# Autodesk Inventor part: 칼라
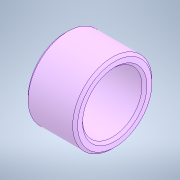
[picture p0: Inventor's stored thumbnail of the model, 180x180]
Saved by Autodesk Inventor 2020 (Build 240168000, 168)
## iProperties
Created: 2024-05
Part Number: 칼라
Material: 강철, 합금
Document SubType Name: Modeling
Designer: oem
Density: 7.73 g/cm^3
Appearance: 기본값
Author: jhkim
Sending System: Autodesk Inventor 2025
Preprocessor: ST-DEVELOPER v20
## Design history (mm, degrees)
feature "솔리드1"
node "솔리드2"
